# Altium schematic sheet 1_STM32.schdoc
size 429 x 307 mm; Symbol: Drawing-Symbol_A4; Device: Drawing-Symbol_A4; @Project Name: Temp_Con_V116; @Page Count: 1; @Update Date: 2025-01-28; @Create Date: 2025-01-21; @Schematic Name: TEMP_STM32; @Page No: 1; @Page Name: STM32; Company: EasyEDA.com; Version: V1.0; Page Size: A4; @Create Time: 08:24:48; @Update Time: 06:57:14; Width: 1655; Height: 1170; Region Start: 1; X Region Count: 6; Y Region Count: 4; Blade Width: 10; Title Block Position: 3; @Board Name: TEMP_STM32
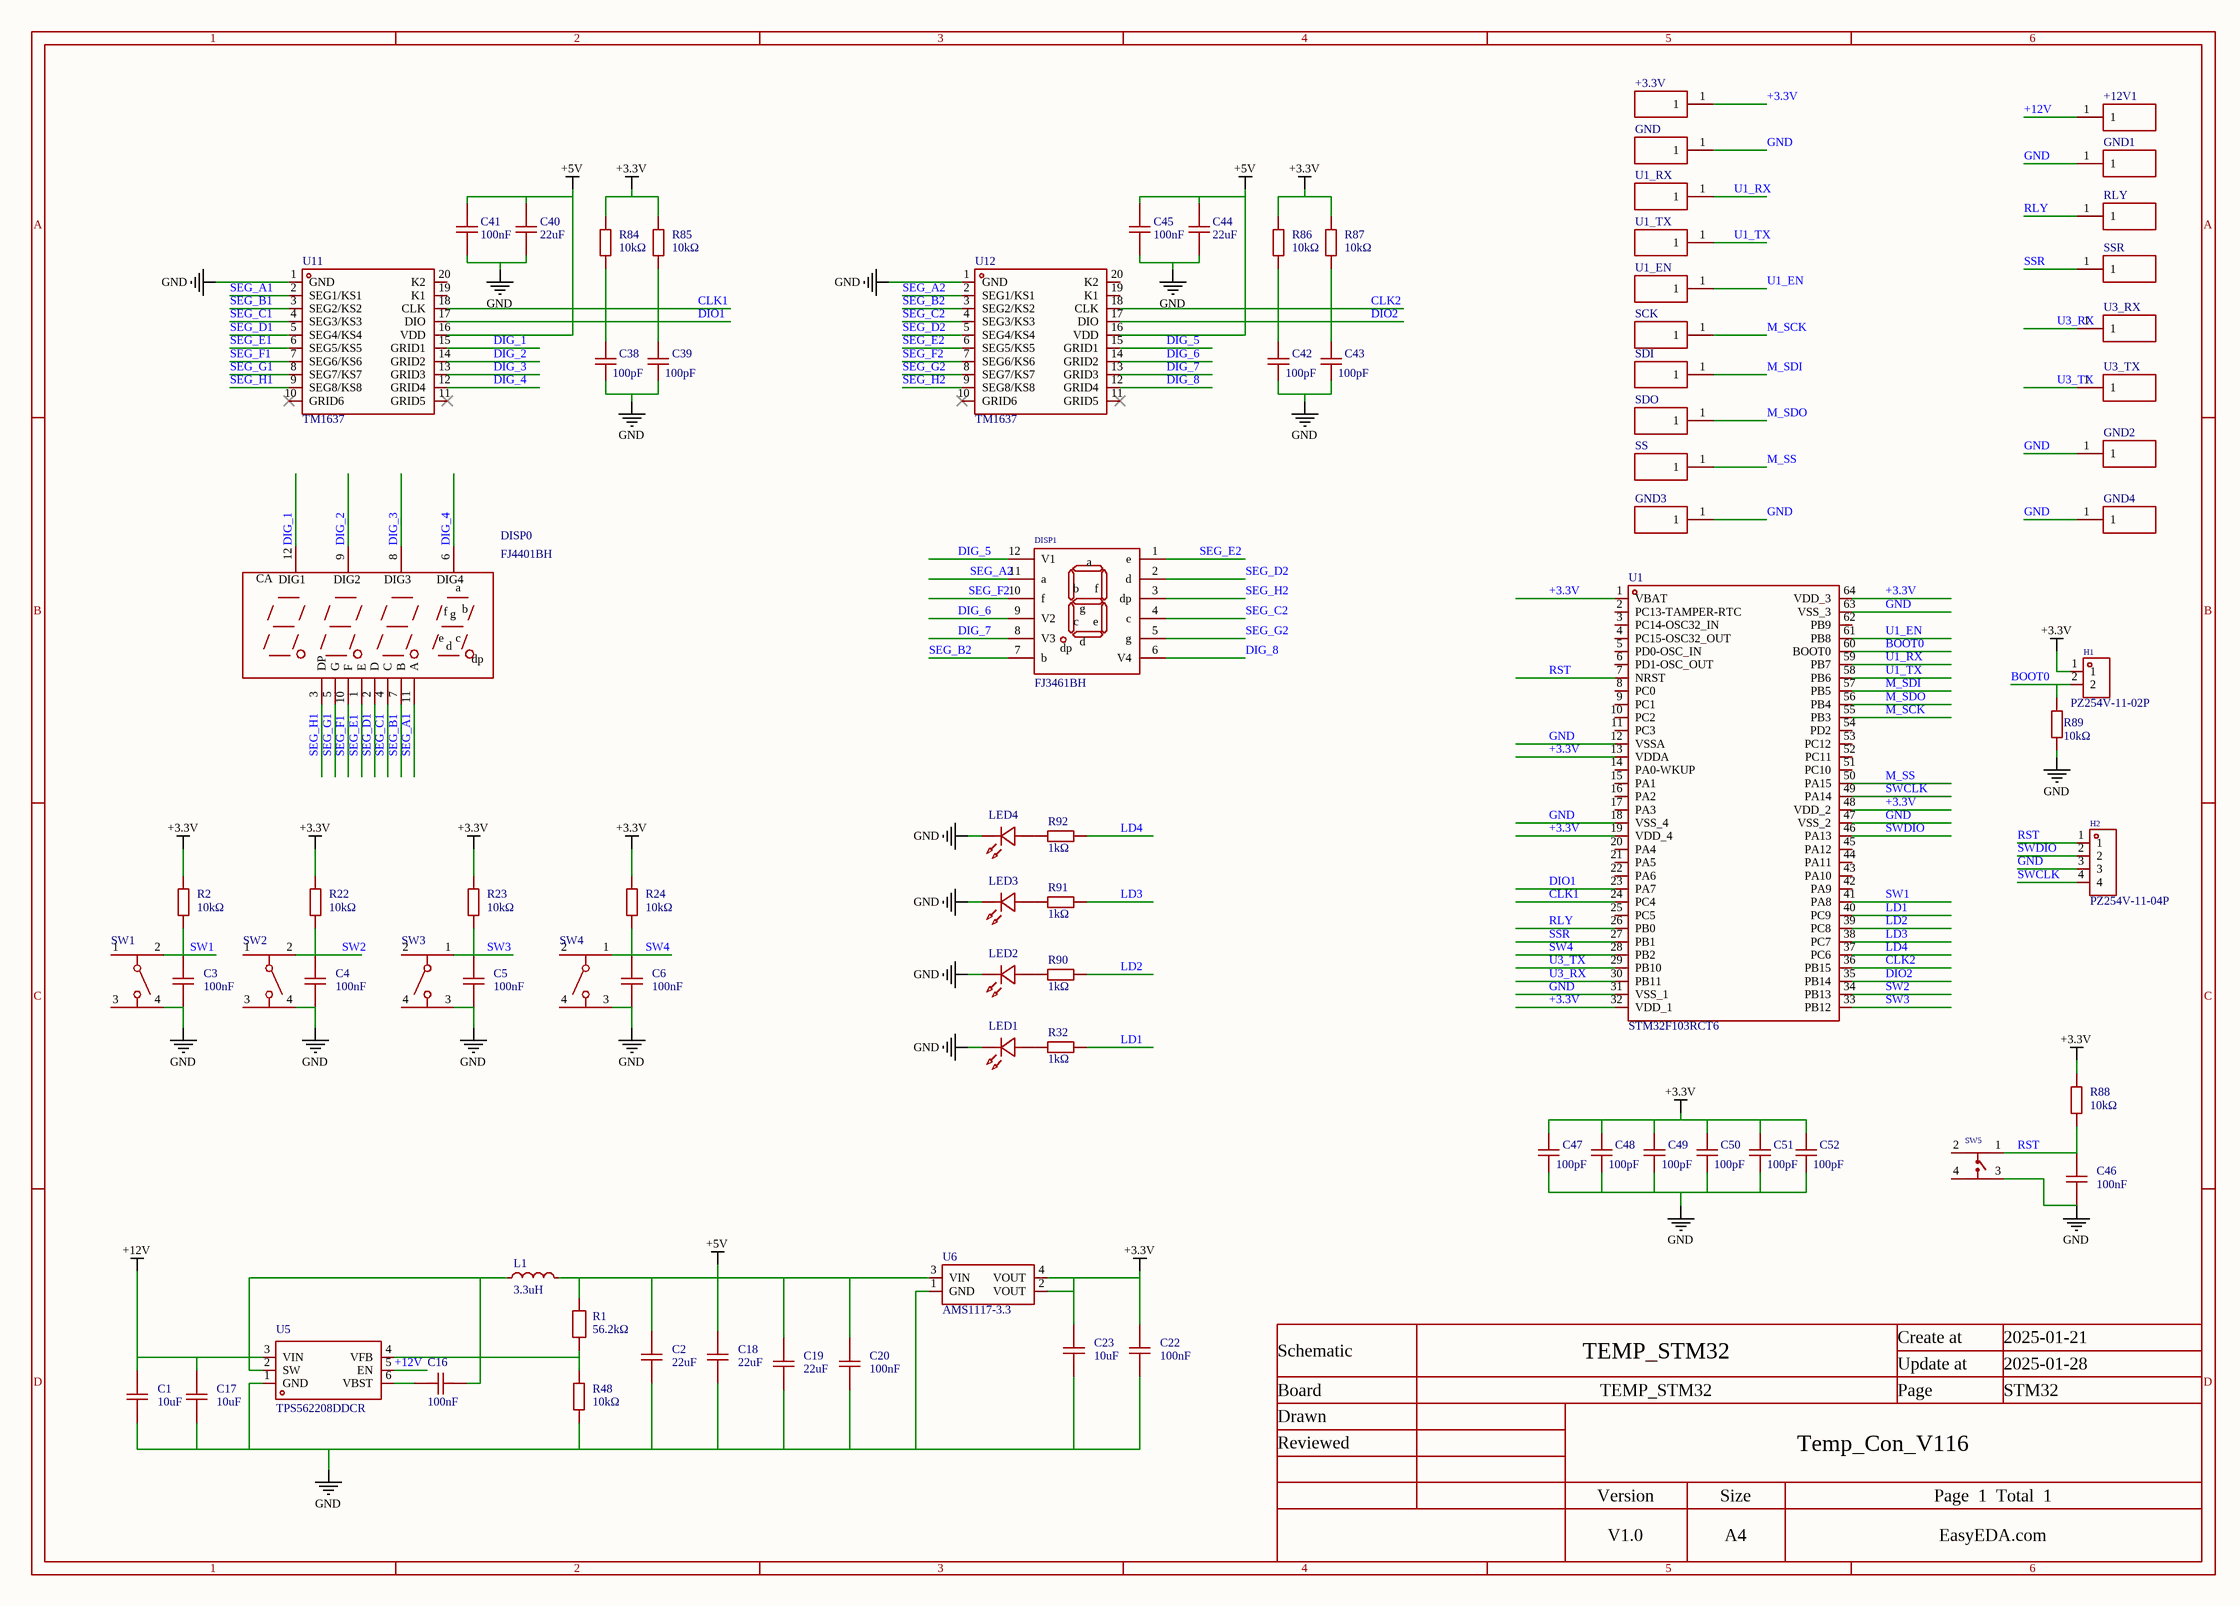
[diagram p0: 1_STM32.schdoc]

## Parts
+3.3V  (no value)  [S_FT]
+12V1  (no value)  [S_FT]
C1  10uF  [C1210]
C2  22uF  [C0805]
C3  100nF  [C0805]
C4  100nF  [C0805]
C5  100nF  [C0805]
C6  100nF  [C0805]
C16  100nF  [C0805]
C17  10uF  [C1210]
C18  22uF  [C0805]
C19  22uF  [C0805]
C20  100nF  [C0805]
C22  100nF  [C0805]
C23  10uF  [C0805]
C38  100pF  [C0805]
C39  100pF  [C0805]
C40  22uF  [C0805]
C41  100nF  [C0805]
C42  100pF  [C0805]
C43  100pF  [C0805]
C44  22uF  [C0805]
C45  100nF  [C0805]
C46  100nF  [C0805]
C47  100pF  [C0805]
C48  100pF  [C0805]
C49  100pF  [C0805]
C50  100pF  [C0805]
C51  100pF  [C0805]
C52  100pF  [C0805]
DISP0  FJ4401BH  [LED-SEG-TH_12P-L40.4-W16.0-P2.54-S12.70-BL]
DISP1  FJ3461BH  [LED-SEG-TH_12P-L30.0-W13.7-P2.54-S10.16-BL]
GND  (no value)  [S_FT]
GND1  (no value)  [S_FT]
GND2  (no value)  [S_FT]
GND3  (no value)  [S_FT]
GND4  (no value)  [S_FT]
H1  PZ254V-11-02P  [HDR-TH_2P-P2.54-V-M]
H2  PZ254V-11-04P  [HDR-TH_4P-P2.54-V-M]
L1  3.3uH  [IND-SMD_L5.4-W5.2_RS0530]
LED1  XL-2012SURC  [LED0805-R-RD]  (value not drawn)
LED2  XL-2012SURC  [LED0805-R-RD]  (value not drawn)
LED3  XL-2012SURC  [LED0805-R-RD]  (value not drawn)
LED4  XL-2012SURC  [LED0805-R-RD]  (value not drawn)
R1  56.2kΩ  [R0805]
R2  10kΩ  [R0805]
R22  10kΩ  [R0805]
R23  10kΩ  [R0805]
R24  10kΩ  [R0805]
R32  1kΩ  [R0805]
R48  10kΩ  [R0805]
R84  10kΩ  [R0805]
R85  10kΩ  [R0805]
R86  10kΩ  [R0805]
R87  10kΩ  [R0805]
R88  10kΩ  [R0805]
R89  10kΩ  [R0805]
R90  1kΩ  [R0805]
R91  1kΩ  [R0805]
R92  1kΩ  [R0805]
RLY  (no value)  [S_FT]
SCK  (no value)  [S_FT]
SDI  (no value)  [S_FT]
SDO  (no value)  [S_FT]
SS  (no value)  [S_FT]
SSR  (no value)  [S_FT]
SW1  YTS1R0011FBT00  [SW-TH_4P-L6.0-W6.0-P4.50-LS6.5]  (value not drawn)
SW2  YTS1R0011FBT00  [SW-TH_4P-L6.0-W6.0-P4.50-LS6.5]  (value not drawn)
SW3  YTS1R0011FBT00  [SW-TH_4P-L6.0-W6.0-P4.50-LS6.5]  (value not drawn)
SW4  YTS1R0011FBT00  [SW-TH_4P-L6.0-W6.0-P4.50-LS6.5]  (value not drawn)
SW5  TSC005A1618A03  [KEY-SMD_4P-L5.2-W5.2-P3.70-LS6.4]  (value not drawn)
U1  STM32F103RCT6  [LQFP-64_L10.0-W10.0-P0.50-LS12.0-BL]
U1_EN  (no value)  [S_FT]
U1_RX  (no value)  [S_FT]
U1_TX  (no value)  [S_FT]
U3_RX  (no value)  [S_FT]
U3_TX  (no value)  [S_FT]
U5  TPS562208DDCR  [SOT-23-6_L2.9-W1.6-P0.95-LS2.8-BR]
U6  AMS1117-3.3  [SOT-223-3_L6.5-W3.4-P2.30-LS7.0-BR]
U11  TM1637  [SOP-20_L12.8-W7.5-P1.27-LS10.4-BL]
U12  TM1637  [SOP-20_L12.8-W7.5-P1.27-LS10.4-BL]

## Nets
+3.3V: +3.3V.1 C22.2 C23.2 C47.2 C48.2 C49.2 C50.2 C51.2 C52.2 H1.1 R2.2 R22.2 R23.2 R24.2 R84.2 R85.2 R86.2 R87.2 R88.2 U1.1(VBAT) U1.13(VDDA) U1.19(VDD_4) U1.32(VDD_1) U1.48(VDD_2) U1.64(VDD_3) U6.2(VOUT) U6.4(VOUT)
+5V: C2.2 C18.2 C19.2 C20.2 C40.2 C41.2 C44.2 C45.2 L1.2 R1.1 U6.3(VIN) U11.16(VDD) U12.16(VDD)
+12V: +12V1.1 C1.2 C17.2 U5.3(VIN) U5.5(EN)
GND: C1.1 C2.1 C3.1 C4.1 C5.1 C6.1 C17.1 C18.1 C19.1 C20.1 C22.1 C23.1 C38.1 C39.1 C40.1 C41.1 C42.1 C43.1 C44.1 C45.1 C46.1 C47.1 C48.1 C49.1 C50.1 C51.1 C52.1 GND.1 GND1.1 GND2.1 GND3.1 GND4.1 H2.3 LED1.2(K) LED2.2(K) LED3.2(K) LED4.2(K) R48.1 R89.1 SW1.4 SW2.4 SW3.3 SW4.3 SW5.3 U1.12(VSSA) U1.18(VSS_4) U1.31(VSS_1) U1.47(VSS_2) U1.63(VSS_3) U5.1(GND) U6.1(GND) U11.1(GND) U12.1(GND)
BOOT0: H1.2 R89.2 U1.60(BOOT0)
CLK1: C38.2 R84.1 U1.24(PC4) U11.18(CLK)
CLK2: C42.2 R86.1 U1.36(PB15) U12.18(CLK)
DIG_1: DISP0.12(DIG1) U11.15(GRID1)
DIG_2: DISP0.9(DIG2) U11.14(GRID2)
DIG_3: DISP0.8(DIG3) U11.13(GRID3)
DIG_4: DISP0.6(DIG4) U11.12(GRID4)
DIG_5: DISP1.12(V1) U12.15(GRID1)
DIG_6: DISP1.9(V2) U12.14(GRID2)
DIG_7: DISP1.8(V3) U12.13(GRID3)
DIG_8: DISP1.6(V4) U12.12(GRID4)
DIO1: C39.2 R85.1 U1.23(PA7) U11.17(DIO)
DIO2: C43.2 R87.1 U1.35(PB14) U12.17(DIO)
LD1: R32.2 U1.40(PC9)
LD2: R90.2 U1.39(PC8)
LD3: R91.2 U1.38(PC7)
LD4: R92.2 U1.37(PC6)
M_SCK: SCK.1 U1.55(PB3)
M_SDI: SDI.1 U1.57(PB5)
M_SDO: SDO.1 U1.56(PB4)
M_SS: SS.1 U1.50(PA15)
RLY: RLY.1 U1.26(PB0)
RST: C46.2 H2.1 R88.1 SW5.1 U1.7(NRST)
SEG_A1: DISP0.11(A) U11.2(SEG1/KS1)
SEG_A2: DISP1.11(a) U12.2(SEG1/KS1)
SEG_B1: DISP0.7(B) U11.3(SEG2/KS2)
SEG_B2: DISP1.7(b) U12.3(SEG2/KS2)
SEG_C1: DISP0.4(C) U11.4(SEG3/KS3)
SEG_C2: DISP1.4(c) U12.4(SEG3/KS3)
SEG_D1: DISP0.2(D) U11.5(SEG4/KS4)
SEG_D2: DISP1.2(d) U12.5(SEG4/KS4)
SEG_E1: DISP0.1(E) U11.6(SEG5/KS5)
SEG_E2: DISP1.1(e) U12.6(SEG5/KS5)
SEG_F1: DISP0.10(F) U11.7(SEG6/KS6)
SEG_F2: DISP1.10(f) U12.7(SEG6/KS6)
SEG_G1: DISP0.5(G) U11.8(SEG7/KS7)
SEG_G2: DISP1.5(g) U12.8(SEG7/KS7)
SEG_H1: DISP0.3(DP) U11.9(SEG8/KS8)
SEG_H2: DISP1.3(dp) U12.9(SEG8/KS8)
SSR: SSR.1 U1.27(PB1)
SW1: C3.2 R2.1 SW1.2 U1.41(PA8)
SW2: C4.2 R22.1 SW2.2 U1.34(PB13)
SW3: C5.2 R23.1 SW3.1 U1.33(PB12)
SW4: C6.2 R24.1 SW4.1 U1.28(PB2)
SWCLK: H2.4 U1.49(PA14)
SWDIO: H2.2 U1.46(PA13)
U1_EN: U1.61(PB8) U1_EN.1
U1_RX: U1.59(PB7) U1_RX.1
U1_TX: U1.58(PB6) U1_TX.1
U3_RX: U1.30(PB11) U3_RX.1
U3_TX: U1.29(PB10) U3_TX.1
NetC16_1: C16.1 U5.6(VBST)
NetC16_2: C16.2 L1.1 U5.2(SW)
NetLED1_1: LED1.1(A) R32.1
NetLED2_1: LED2.1(A) R90.1
NetLED3_1: LED3.1(A) R91.1
NetLED4_1: LED4.1(A) R92.1
NetR1_2: R1.2 R48.2 U5.4(VFB)

Not connected (* = marked no-connect by the designer): SW1 1 3; SW2 1 3; SW3 2 4; SW4 2 4; SW5 2 4; U1 2(PC13-TAMPER-RTC) 3(PC14-OSC32_IN) 4(PC15-OSC32_OUT) 5(PD0-OSC_IN) 6(PD1-OSC_OUT) 8(PC0) 9(PC1) 10(PC2) 11(PC3) 14(PA0-WKUP) 15(PA1) 16(PA2) 17(PA3) 20(PA4) 21(PA5) 22(PA6) 25(PC5) 42(PA9) 43(PA10) 44(PA11) 45(PA12) 51(PC10) 52(PC11) 53(PC12) 54(PD2) 62(PB9); U11 10(GRID6)* 11(GRID5)* 19(K1) 20(K2); U12 10(GRID6)* 11(GRID5)* 19(K1) 20(K2)

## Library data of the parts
+3.3V +12V1 GND GND1-GND4 RLY SCK SDI SDO SS SSR U1_EN U1_RX U1_TX U3_RX U3_TX = S_TM: Add into BOM: no
C1 C17 = CS3225X7R106K500NRL: Manufacturer: SAMWHA(三和); Add into BOM: yes
C2 C18 C19 C40 C44 = GRM21BZ71A226ME15L: Manufacturer: muRata(村田); Add into BOM: yes; Tolerance: ±20%
C3-C6 C16 C20 C22 C41 C45 C46 = CC0805KRX7R9BB104: Manufacturer: YAGEO(国巨); Add into BOM: yes; Tolerance: ±10%
C23 = GRM21BR61C106KE15L: Manufacturer: muRata(村田); Add into BOM: yes; Tolerance: ±10%
C38 C39 C42 C43 C47-C52 = CC0805KRX7R9BB101: Manufacturer: YAGEO(国巨); Add into BOM: yes; Tolerance: ±10%; Check: true
DISP0 = FJ4401BH: Manufacturer: 志浩; Add into BOM: yes; Number of Characters: 4Bit; Luminous Color: Red; LED Polarity: 共阳极; Digit/Alpha Size(inch): 0.4; Check: true
DISP1 = FJ3461BH: Manufacturer: 志浩; Add into BOM: yes; Number of Characters: 4Bit; Luminous Color: Red; LED Polarity: 共阳极; Digit/Alpha Size(inch): 0.36; Check: true
H1 = PZ254V-11-02P: Manufacturer: XFCN(兴飞); Add into BOM: yes; Pin Structure: 1x2P; Pitch: 2.54mm; Circluar Pins/Square Pins: Square Pins; Check: true
H2 = PZ254V-11-04P: Manufacturer: XFCN(兴飞); Symbol: PZ254V-11-04P_C2691448; Add into BOM: yes; Pin Structure: 1x4P; Pitch: 2.54mm; Circluar Pins/Square Pins: Square Pins; Current Rating (Max): 3A; Voltage Rating (Max): 250V; Check: true
L1 = RS0530-3R3MS: Manufacturer: Ruishen(瑞申电子); Add into BOM: yes; Tolerance: ±20%; Current - Saturation (Isat): 6A; Type: Integrated molded inductor; Check: true
LED1-LED4 = XL-2012SURC: Manufacturer: XINGLIGHT(成兴光); Add into BOM: yes; Emitted Color: Red; Power Dissipation: 55mW; Forward Current: 25mA; Dominant Wavelength: 617nm~621nm; Peak Wavelength: 623nm; Lens Color: 无色透明透镜; Viewing Angle: 120°; Mounting Sytle: Positive post; Check: true
R1 = RC0805FR-0756K2L: Manufacturer: YAGEO(国巨); Add into BOM: yes; Tolerance: ±1%; Temperature Coefficient: ±100ppm/℃
R2 R22-R24 R48 R84-R89 = RC0805FR-0710KL: Manufacturer: YAGEO(国巨); Add into BOM: yes; Tolerance: ±1%; Temperature Coefficient: ±100ppm/℃
R32 R90-R92 = RC0805FR-071KL: Manufacturer: YAGEO(国巨); Add into BOM: yes; Tolerance: ±1%; Temperature Coefficient: ±100ppm/℃
SW1-SW4 = YTS1R0011FBT00: Manufacturer: YIYUAN(怡远); Add into BOM: yes; Circuit: SPST; Actuator Style: Round Button; Operating Force: 160gf; Switch Length: 6mm; Switch Height: 7mm; Contact Current: 50mA; Voltage Rating (DC): 12V; Check: true
SW5 = TSC005A1618A03: Manufacturer: BZCN(博众电气); Add into BOM: yes; Actuator Style: Round Button; Operating Force: 180gf; Switch Length: 5.2mm; Switch Height: 1.6mm; Contact Current: 50mA; Voltage Rating (DC): 12V; Check: true
U1 = STM32F103RCT6: Manufacturer: ST(意法半导体); Add into BOM: yes; CPU Core: ARM-M3; CPU Maximum Speed: 72MHz; Program Storage Size: 256KB; Program Memory Type: FLASH; Number of I/O: 51; ADC (Bit): 12bit; Low Voltage Detection Threshold: 2V~3.6V; Check: true
U5 = TPS562208DDCR: Manufacturer: TI(德州仪器); Add into BOM: yes; Function: Step-down type; Output Type: Adjustable; Input Voltage: 4.5V~17V; Output Voltage: 760mV~7V; Output Current: 2A; Switching Frequency: 580kHz; Number of Outputs: 1; Topology: Step-down; Quiescent Current (Iq): 10uA; Switch tube (built-in/external): Built-in; Check: true
U6 = AMS1117-3.3_C6068481: Manufacturer: GOODWORK(固得沃克); Add into BOM: yes; Output Type: Fixed; Maximum Input Voltage: 18V; Output Voltage: 3.3V; Output Current: 1A; Power Supply Rejection Ratio (PSRR): 70dB@(120Hz); Output Polarity: Positive electrode; Number of Outputs: 1; Check: true
U11 U12 = TM1637: Manufacturer: TM(天微); Symbol: TM1637_C2962580; Add into BOM: yes; Check: true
